// Mitsubishi GX Works2 project: MC-20MR-6MT-FE430A-JK3U-A例程   PLC: FX3U/FX3UC

PROGRAM MAIN
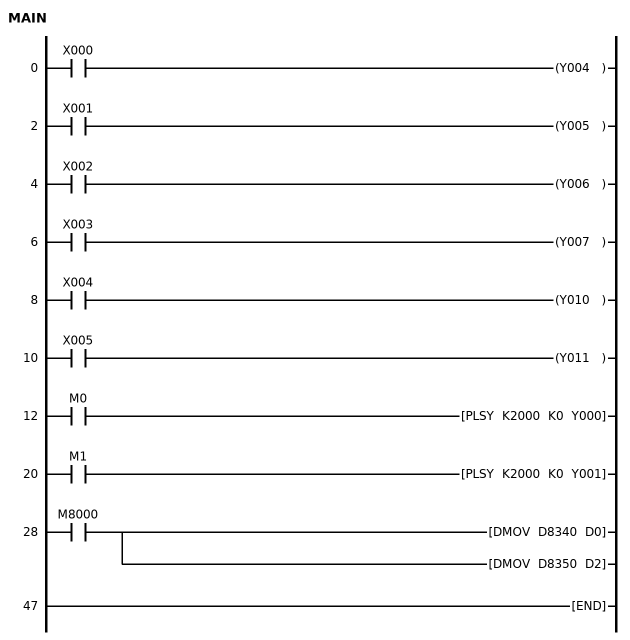
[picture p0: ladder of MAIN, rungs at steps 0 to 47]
0     LD      X000
      OUT     Y004
2     LD      X001
      OUT     Y005
4     LD      X002
      OUT     Y006
6     LD      X003
      OUT     Y007
8     LD      X004
      OUT     Y010
10    LD      X005
      OUT     Y011
12    LD      M0
      PLSY    K2000 K0 Y000
20    LD      M1
      PLSY    K2000 K0 Y001
28    LD      M8000
      DMOV    D8340 D0
      DMOV    D8350 D2
47    END
END_PROGRAM
